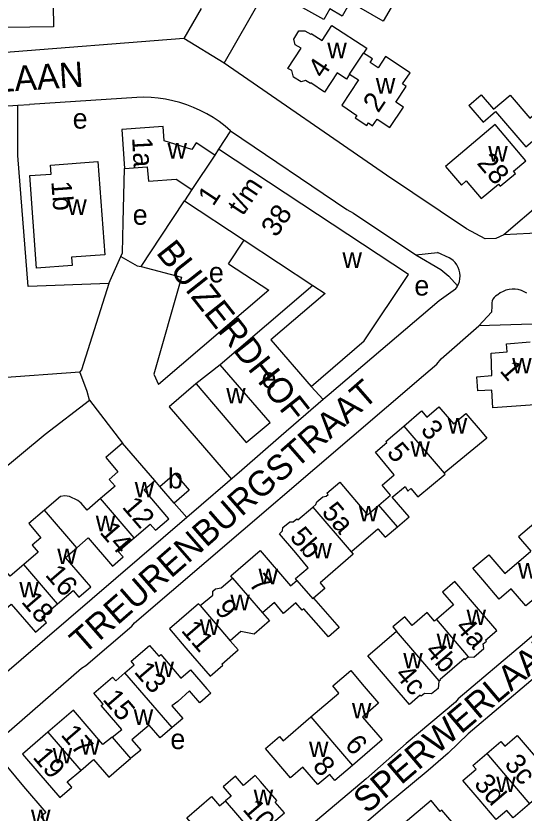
# Model space of a CAD drawing. Extents: x 161775 to 163181, y 382878 to 383925.
# Drawn here: x 162330.5 to 162431.4, y 383379.1 to 383537.4 of the extents above; entities that cross this region are included whole.
import ezdxf

# ---------------------------------------------------------------- set-up
doc = ezdxf.new("R2010")
doc.units = 0
for name, color, linetype in [('BLT_Basislijn', 7, 'Continuous'), ('BLT_Bebouwing', 7, 'Continuous'), ('BLT_Centroide', 7, 'Continuous'), ('BLT_Huisnummer', 7, 'Continuous'), ('BLT_Huisnummer_ tussenligend', 7, 'Continuous'), ('BLT_Huisnummer_reeks', 7, 'Continuous'), ('BLT_Onderverdeling_panden', 7, 'Continuous'), ('BLT_Straatnaam', 7, 'Continuous'), ('BLT_Vlakafsluiter', 7, 'Continuous')]:
    doc.layers.add(name, color=color, linetype=linetype)

msp = doc.modelspace()

# ---------------------------------------------------------------- linework, layer by layer
at = {"layer": 'BLT_Basislijn'}
for p, q in [((162371.87, 383527.99), (162382.43, 383546.52)), ((162367.27, 383538.86), (162363.82, 383532.92)), ((162363.82, 383532.92), (162326.4, 383529.95)), ((162404.09, 383505.78), (162371.87, 383527.99)), ((162326.23, 383519.34), (162330.87, 383519.66)), ((162330.87, 383519.66), (162333.17, 383519.81)), ((162354.48, 383521.19), (162333.17, 383519.81)), ((162457.69, 383519.94), (162427.38, 383493.93)), ((162373.13, 383514.58), (162370.75, 383510.9)), ((162420, 383495.12), (162404.09, 383505.78)), ((162359.34, 383493.66), (162363.97, 383500.65)), ((162423.66, 383493.13), (162420, 383495.12)), ((162372.71, 383488.18), (162375.8, 383492.86)), ((162425.81, 383493.17), (162423.66, 383493.13)), ((162427.38, 383493.93), (162425.81, 383493.17)), ((162348.94, 383484.25), (162351.33, 383489.59)), ((162409.9, 383489.96), (162414.18, 383490.39)), ((162409.9, 383489.96), (162414.9, 383487.01)), ((162416.54, 383489.36), (162414.18, 383490.39)), ((162372.71, 383488.18), (162380.72, 383482.91)), ((162354.57, 383487.77), (162355.35, 383487.64)), ((162355.35, 383487.64), (162363.39, 383485.52)), ((162363.39, 383485.52), (162357.86, 383466.22)), ((162389.47, 383483.86), (162371.03, 383468.13)), ((162380.72, 383482.91), (162358.81, 383464.21)), ((162417.76, 383483.13), (162414.52, 383480.78)), ((162439.94, 383476.36), (162422.42, 383475.81)), ((162282.95, 383462.44), (162343.17, 383466.7)), ((162357.86, 383466.22), (162358.81, 383464.21)), ((162366.24, 383464.35), (162360.91, 383459.75)), ((162389.1, 383463.77), (162391.49, 383461.2)), ((162345.08, 383461.11), (162351.68, 383452.54)), ((162391.49, 383461.2), (162383.2, 383453.99)), ((162360.91, 383459.75), (162373.3, 383445.39)), ((162359.11, 383443.95), (162358.08, 383445.1)), ((162364.43, 383437.79), (162361.95, 383440.66)), ((162364.43, 383437.79), (162308.93, 383390.15))]:
    msp.add_line(p, q, dxfattribs=at)
for points in [[(162373.13, 383514.58), (162372.02, 383515.52), (162370.85, 383516.39), (162369.64, 383517.19), (162368.39, 383517.93), (162367.1, 383518.6), (162365.78, 383519.19), (162364.42, 383519.71), (162363.04, 383520.16), (162361.63, 383520.53), (162360.21, 383520.82), (162358.77, 383521.03), (162357.33, 383521.16), (162355.88, 383521.22), (162354.48, 383521.19)], [(162332.94, 383483.65), (162330.87, 383509.66), (162330.87, 383519.66)], [(162373.13, 383514.58), (162396.2, 383498.97), (162397.54, 383498.24), (162409.9, 383489.96)], [(162351.33, 383489.59), (162351.67, 383490.34), (162351.82, 383496.43), (162352.09, 383507.07)], [(162355.35, 383487.64), (162359.34, 383493.66)], [(162351.33, 383489.59), (162354.57, 383487.77)], [(162418.19, 383483.78), (162418.36, 383484.1), (162418.55, 383484.64), (162418.67, 383485.2), (162418.71, 383485.77), (162418.66, 383486.34), (162418.54, 383486.9), (162418.34, 383487.44), (162418.07, 383487.94), (162417.73, 383488.4), (162417.33, 383488.81), (162416.88, 383489.16), (162416.54, 383489.36)], [(162414.9, 383487.01), (162416.43, 383485.68), (162418.19, 383483.78)], [(162348.94, 383484.25), (162332.94, 383483.65)], [(162348.94, 383484.25), (162343.51, 383467.08), (162343.17, 383466.7)], [(162417.76, 383483.13), (162418.1, 383483.59), (162418.19, 383483.78)], [(162426.04, 383481.9), (162425.71, 383481.71), (162425.43, 383481.45), (162425.2, 383481.14), (162425.05, 383480.79), (162424.97, 383480.42), (162424.97, 383480.03), (162425.02, 383479.76)], [(162431.97, 383482.31), (162431.43, 383482.62), (162430.86, 383482.87), (162430.26, 383483.03), (162429.65, 383483.12), (162429.02, 383483.13), (162428.41, 383483.06), (162427.8, 383482.91), (162427.22, 383482.68), (162426.68, 383482.39), (162426.18, 383482.02), (162426.04, 383481.9)], [(162414.52, 383480.78), (162392.68, 383462.23), (162391.49, 383461.2)], [(162425.02, 383479.76), (162424.92, 383478.53), (162422.42, 383475.81)], [(162458.26, 383455.1), (162467.27, 383444.75), (162467.36, 383443.86), (162431.49, 383412.9), (162418.33, 383401.81), (162417.78, 383401.1), (162408.01, 383392.9), (162400.04, 383385.87), (162360.11, 383352.24), (162353.15, 383345.86), (162352.04, 383345.68), (162316.39, 383381.73), (162316.3, 383384.27), (162343.54, 383407.84), (162344.4, 383408.4), (162353.54, 383416.23), (162354.02, 383416.86), (162411.46, 383465.98), (162414.05, 383468.24), (162414.93, 383469.26), (162422.42, 383475.81)], [(162345.08, 383461.11), (162344.65, 383462.79), (162343.17, 383466.7)], [(162286.02, 383413.98), (162326.83, 383446.53), (162336.32, 383454.32), (162345.08, 383461.11)], [(162383.2, 383453.99), (162375.35, 383447.16), (162364.43, 383437.79)], [(162495.64, 383411.76), (162472.36, 383438.61), (162471.64, 383438.47), (162459.3, 383427.81), (162454.29, 383423.76), (162452.92, 383422.41), (162420.3, 383394.84), (162416.34, 383390.96), (162412.36, 383387.52), (162403.8, 383380.46), (162382.22, 383361.95), (162376.07, 383356.94), (162357.64, 383341.11), (162357.5, 383340.43), (162364.56, 383332.99), (162388.13, 383309.03), (162393.36, 383303.95)]]:
    msp.add_lwpolyline(points, dxfattribs=at)
at = {"layer": 'BLT_Bebouwing'}
for p, q in [((162370.75, 383510.9), (162369.98, 383509.74)), ((162365.46, 383502.91), (162363.97, 383500.65)), ((162363.97, 383500.65), (162375.8, 383492.86)), ((162366.24, 383464.35), (162366.28, 383464.3)), ((162366.28, 383464.3), (162376.21, 383452.69)), ((162376.21, 383452.69), (162380.96, 383456.62)), ((162358.08, 383445.1), (162351.68, 383452.54)), ((162361.95, 383440.66), (162359.11, 383443.95))]:
    msp.add_line(p, q, dxfattribs=at)
for points in [[(162321, 383571.11), (162328.99, 383571.18), (162328.95, 383575.83), (162340.08, 383575.93), (162340.18, 383563.69), (162340.29, 383558.17), (162340.51, 383539.52), (162337.92, 383539.49), (162337.98, 383535.18), (162323.79, 383535), (162323.75, 383537.58), (162320.5, 383537.54), (162320.54, 383534.87)], [(162404.54, 383539.34), (162405.01, 383539.07), (162403.43, 383536.32), (162396.89, 383540.09), (162395.3, 383537.34), (162392.84, 383538.76), (162391.62, 383536.64), (162387.5, 383539.01), (162388.73, 383541.13), (162386.93, 383542.16), (162387.87, 383544.22), (162389.01, 383545.56), (162390.3, 383547.8)], [(162396.77, 383525.83), (162396.11, 383524.84), (162394.29, 383526.06), (162391.75, 383522.25), (162389.09, 383524.09), (162389.01, 383523.95), (162387.99, 383524.54), (162387.16, 383524.32), (162385.65, 383525.19), (162385.3, 383526.51), (162384.51, 383526.96), (162387.16, 383530.97), (162385.96, 383531.66), (162385.67, 383532.75), (162386.65, 383534.45), (162387.84, 383534.45), (162389.03, 383533.77), (162389.13, 383533.92), (162391.32, 383532.51), (162393.21, 383535.47), (162400.2, 383530.98), (162399.55, 383530)], [(162407.43, 383519.24), (162405.91, 383520.26), (162407.99, 383523.39), (162407.28, 383523.87), (162408.76, 383526.09), (162403.9, 383529.32), (162402.4, 383527.07), (162400.82, 383528.12), (162401.3, 383528.83), (162399.55, 383530)], [(162396.77, 383525.83), (162398.52, 383524.66), (162395.19, 383519.65), (162398.22, 383517.64), (162397.89, 383517.13), (162400.15, 383515.63), (162400.48, 383516.12), (162401.31, 383515.57), (162402.2, 383516.91), (162404.75, 383515.21), (162407.43, 383519.24)], [(162420.44, 383519.57), (162422.9, 383521.69), (162425.36, 383518.84), (162428.62, 383521.65), (162432.56, 383517.06), (162435.02, 383519.17), (162433.32, 383521.15), (162436.84, 383524.17)], [(162420.44, 383519.57), (162423.28, 383516.27), (162425.74, 383518.39), (162431.77, 383511.38), (162434.86, 383514.04), (162438.91, 383509.34), (162445.06, 383514.63), (162444.71, 383515.04)], [(162369.98, 383509.74), (162366.29, 383512.16), (162365.41, 383510.83), (162359.94, 383512.6), (162359.75, 383515.42), (162351.52, 383514.81), (162352.09, 383507.07)], [(162428.52, 383512.42), (162425.65, 383515.81), (162419.65, 383510.72), (162415.83, 383507.49), (162418.96, 383503.8), (162419.93, 383504.63), (162422.9, 383501.13), (162426.29, 383504), (162426.68, 383503.55), (162429.68, 383506.1), (162429.31, 383506.54), (162431.75, 383508.61), (162428.52, 383512.42)], [(162389.1, 383463.77), (162399.68, 383472.84), (162408.44, 383486.05), (162387.28, 383500), (162370.75, 383510.9)], [(162333.26, 383505.67), (162337.52, 383505.98), (162337.39, 383507.77), (162346.79, 383508.46), (162348.15, 383489.95), (162341.53, 383489.47), (162341.65, 383487.79), (162334.61, 383487.27), (162333.26, 383505.67)], [(162352.09, 383507.07), (162356.59, 383507.41), (162356.8, 383504.58), (162362.31, 383504.99), (162365.46, 383502.91)], [(162375.8, 383492.86), (162389.47, 383483.86)], [(162389.47, 383483.86), (162391.9, 383482.25), (162381.15, 383473.04), (162389.1, 383463.77)], [(162433.51, 383460.4), (162433.51, 383460.13), (162425.23, 383459.57), (162424.98, 383463.1), (162422.25, 383462.91), (162422.04, 383465.74), (162425.02, 383465.96), (162424.88, 383470.43), (162428.02, 383470.66), (162427.91, 383472.3), (162432.62, 383472.64)], [(162380.96, 383456.62), (162371.03, 383468.13), (162366.24, 383464.35)], [(162407.52, 383455.9), (162411.06, 383458.94), (162412.11, 383457.72), (162414.5, 383459.78), (162417.42, 383456.38), (162419.81, 383458.44), (162423.07, 383454.64), (162424.01, 383453.55), (162415.51, 383446.6)], [(162402.53, 383440.23), (162404.88, 383442.25), (162403.21, 383444.2), (162405.6, 383446.25), (162401.91, 383450.75), (162404.14, 383452.66), (162403.98, 383452.85), (162407.52, 383455.9)], [(162351.68, 383452.54), (162348.34, 383449.67), (162350.75, 383446.86), (162349.01, 383445.36), (162350.18, 383443.99), (162347.32, 383441.53)], [(162359.11, 383443.95), (162362.06, 383446.49), (162364.9, 383443.19), (162361.95, 383440.66)], [(162406.24, 383435.92), (162408.56, 383437.92), (162405.22, 383441.8), (162407.79, 383443.94), (162408.31, 383443.04), (162408.93, 383443.55), (162410.3, 383441.9), (162415.7, 383446.38), (162415.51, 383446.6)], [(162354, 383433.76), (162357.17, 383436.48), (162358.22, 383435.26), (162360.87, 383437.54), (162355.95, 383443.26), (162358.08, 383445.1)], [(162389.44, 383439.84), (162390.08, 383440.39), (162390.25, 383440.89), (162391.43, 383441.9), (162392.1, 383442.03), (162392.47, 383442.35), (162392.26, 383442.6), (162394.79, 383444.78), (162400.32, 383438.33), (162402.53, 383440.23)], [(162347.32, 383441.53), (162344.65, 383439.24), (162343.47, 383440.61), (162342.79, 383441.19), (162341.12, 383441.94), (162340.23, 383442.08), (162339.34, 383441.95), (162336.21, 383439.26)], [(162438.81, 383424.03), (162442.28, 383426.99), (162441.23, 383428.23), (162443.66, 383430.3), (162440.76, 383433.7), (162443.16, 383435.75), (162439.91, 383439.55), (162437.93, 383441.87), (162434.82, 383439.21), (162435.52, 383438.39), (162430.3, 383433.92), (162432.73, 383431.07)], [(162336.21, 383439.26), (162333.08, 383436.57), (162335.48, 383433.76), (162333.74, 383432.26), (162334.91, 383430.9), (162332.06, 383428.45)], [(162386.29, 383425.3), (162385.99, 383425.65), (162388.52, 383427.82), (162386.07, 383430.77), (162382.81, 383434.56), (162383.46, 383435.12), (162383.51, 383435.78), (162384.87, 383436.95), (162385.52, 383436.9), (162386.27, 383437.54), (162386.47, 383437.3), (162389.44, 383439.84)], [(162397.06, 383430.98), (162397.19, 383431.09), (162402.38, 383435.55), (162403.84, 383433.85), (162406.24, 383435.92)], [(162342.63, 383431.79), (162344.88, 383433.73), (162349.68, 383428.15), (162351.77, 383429.95), (162350.83, 383431.03), (162354, 383433.76)], [(162338.76, 383420.65), (162341.84, 383423.31), (162342.98, 383421.98), (162345.38, 383424.05), (162340.38, 383429.86), (162342.63, 383431.79)], [(162373.52, 383425.77), (162373.15, 383426.2), (162379.01, 383431.23), (162385.03, 383424.22), (162386.29, 383425.3)], [(162438.81, 383424.03), (162435.27, 383421.01), (162434.17, 383422.29), (162431.75, 383420.22), (162428.85, 383423.62), (162426.44, 383421.57), (162423.2, 383425.38), (162421.22, 383427.7), (162424.39, 383430.4), (162427.58, 383426.67), (162432.73, 383431.07)], [(162397.06, 383430.98), (162397.47, 383430.49), (162390.9, 383424.84), (162391.87, 383423.7), (162389.62, 383421.76)], [(162332.06, 383428.45), (162329.37, 383426.14), (162328.2, 383427.51), (162326.45, 383426.01), (162324.05, 383428.81), (162320.99, 383426.19)], [(162367.09, 383420.28), (162369.57, 383422.39), (162369.63, 383423.18), (162370.15, 383423.62), (162371.26, 383423.83), (162373.52, 383425.77)], [(162420.3, 383410.15), (162421.41, 383410.06), (162423.44, 383411.8), (162423.28, 383412.7), (162423.92, 383413.25), (162423.77, 383413.42), (162425.99, 383415.32), (162422.75, 383419.12), (162417.66, 383425.09), (162415.18, 383422.97), (162417.36, 383420.42), (162413.99, 383417.54)], [(162389.62, 383421.76), (162394.67, 383415.94), (162392.54, 383414.09), (162387.7, 383419.67), (162387.36, 383419.37), (162386.09, 383420.84), (162383.66, 383418.75), (162381.84, 383420.88), (162379.48, 383418.83)], [(162327.41, 383418.71), (162329.57, 383420.57), (162334.36, 383414.99), (162336.6, 383416.92), (162335.67, 383418), (162338.76, 383420.65)], [(162367.09, 383420.28), (162366.77, 383420.65), (162360.97, 383415.66), (162364.23, 383411.87), (162369.04, 383406.27), (162371.59, 383408.47), (162371.4, 383408.69), (162374.65, 383411.48), (162373.07, 383413.32)], [(162379.48, 383418.83), (162380.84, 383417.24), (162377.83, 383414.65), (162375.16, 383415.12), (162373.07, 383413.32)], [(162413.99, 383417.54), (162413.6, 383417.21), (162412.15, 383418.9), (162409.17, 383416.36), (162407.72, 383418.05), (162405.37, 383416.05), (162406.09, 383415.2)], [(162414.54, 383405.34), (162414.46, 383405.27), (162414.34, 383403.85), (162413.05, 383402.74), (162411.6, 383402.86), (162410.95, 383402.31), (162410.79, 383402.5), (162408.62, 383400.66), (162405.38, 383404.46), (162400.37, 383410.35), (162406.09, 383415.2)], [(162352.16, 383406.95), (162354, 383408.53), (162353.38, 383409.25), (162357.02, 383412.38), (162358.87, 383410.23), (162359.27, 383410.57), (162363.28, 383405.91), (162365.17, 383407.54), (162368.43, 383403.75), (162369.19, 383402.88), (162367, 383401), (162364.98, 383403.35), (162362.67, 383401.27), (162361.47, 383400.41), (162363.63, 383397.9), (162361.51, 383396.08)], [(162414.54, 383405.34), (162414.81, 383405.58), (162414.71, 383405.7), (162419.51, 383409.8), (162419.67, 383409.61), (162420.3, 383410.15)], [(162389.09, 383398.19), (162394.64, 383402.93), (162393.44, 383404.34), (162396.99, 383407.38), (162399.28, 383404.7), (162402.52, 383400.9), (162399.33, 383398.17), (162403.22, 383393.61), (162397.32, 383388.56)], [(162349.61, 383394.17), (162351.52, 383395.71), (162350.71, 383396.64), (162347.45, 383400.43), (162347.83, 383400.75), (162345.99, 383402.89), (162349.71, 383406.09), (162350.33, 383405.38), (162352.16, 383406.95)], [(162349.61, 383394.17), (162347.79, 383392.71), (162341.93, 383399.54), (162336.86, 383395.18)], [(162397.32, 383388.56), (162393.81, 383385.57), (162392.8, 383386.76), (162390.43, 383384.74), (162387.47, 383388.21), (162385.01, 383386.11), (162380.04, 383391.93), (162382.83, 383394.31), (162383.55, 383393.46), (162389.09, 383398.19)], [(162361.51, 383396.08), (162359.14, 383394.04), (162356.99, 383396.54), (162353.54, 383393.63), (162355.29, 383391.61), (162353.27, 383389.91)], [(162336.86, 383395.18), (162331.78, 383390.82), (162335.04, 383387.03), (162339.19, 383382.2), (162341.58, 383384.26), (162340.71, 383385.27), (162343.39, 383387.57)], [(162424.01, 383390.92), (162426.8, 383393.29), (162427.57, 383392.39), (162430.05, 383394.5), (162437.15, 383386.17), (162439.24, 383387.95), (162442.52, 383384.1), (162439.98, 383381.95), (162437.32, 383385.07), (162432.49, 383380.96)], [(162343.39, 383387.57), (162345.92, 383389.75), (162348.94, 383386.23), (162351.49, 383388.42), (162353.27, 383389.91)], [(162432.49, 383380.96), (162429.22, 383378.17), (162428, 383379.6), (162425.89, 383377.81), (162422.51, 383381.78), (162419.27, 383385.59), (162421.86, 383387.8), (162421.22, 383388.55), (162424.01, 383390.92)], [(162341.1, 383370.08), (162337.23, 383366.91), (162322.63, 383381.72), (162322.74, 383383.1), (162328.81, 383388.22), (162332.04, 383384.4), (162336.43, 383379.21), (162335.45, 383378.38), (162338.42, 383374.87), (162340.86, 383376.93), (162344.38, 383372.77), (162341.1, 383370.08)], [(162378.23, 383374.41), (162383.81, 383379.17), (162381.99, 383381.29), (162382.3, 383381.56), (162379.06, 383385.36), (162378.02, 383386.57), (162375.69, 383384.58), (162374.1, 383386.44), (162371.64, 383384.33), (162373.22, 383382.48), (162372.13, 383381.55)], [(162378.23, 383374.41), (162372.66, 383369.65), (162370.86, 383371.76), (162370.45, 383371.4), (162367.2, 383375.2), (162366.16, 383376.42), (162366.03, 383376.31), (162364.43, 383378.18), (162369.33, 383382.37), (162370.91, 383380.51), (162372.13, 383381.55)], [(162413.5, 383369.7), (162414.65, 383370.68), (162416.2, 383368.84), (162420.91, 383372.85), (162418.31, 383375.89), (162415.07, 383379.7), (162414.76, 383379.44), (162412.93, 383381.59), (162407.39, 383376.88)]]:
    msp.add_lwpolyline(points, dxfattribs=at)
at = {"layer": 'BLT_Onderverdeling_panden'}
for p, q in [((162396.77, 383525.83), (162399.55, 383530)), ((162369.98, 383509.74), (162365.46, 383502.91)), ((162407.52, 383455.9), (162415.51, 383446.6)), ((162354, 383433.76), (162347.32, 383441.53)), ((162342.63, 383431.79), (162336.21, 383439.26)), ((162389.44, 383439.84), (162397.06, 383430.97)), ((162406.24, 383435.92), (162402.53, 383440.23)), ((162338.76, 383420.65), (162332.06, 383428.45)), ((162373.52, 383425.77), (162379.48, 383418.83)), ((162367.09, 383420.28), (162373.07, 383413.32)), ((162413.99, 383417.54), (162420.3, 383410.15)), ((162414.54, 383405.34), (162406.09, 383415.2)), ((162361.51, 383396.08), (162352.16, 383406.95)), ((162389.09, 383398.19), (162397.32, 383388.56)), ((162336.86, 383395.18), (162343.39, 383387.57)), ((162349.61, 383394.17), (162353.27, 383389.91)), ((162424.01, 383390.92), (162432.49, 383380.96)), ((162378.23, 383374.41), (162372.13, 383381.55))]:
    msp.add_line(p, q, dxfattribs=at)
msp.add_lwpolyline([(162386.29, 383425.3), (162389.45, 383421.62), (162389.62, 383421.76)], dxfattribs=at)
at = {"layer": 'BLT_Vlakafsluiter'}
for p, q in [((162371.87, 383527.99), (162363.82, 383532.92)), ((162440.69, 383494.57), (162427.38, 383493.93))]:
    msp.add_line(p, q, dxfattribs=at)

# ---------------------------------------------------------------- texts
at = {"layer": 'BLT_Centroide'}
for s, p in [('w', (162392.33, 383528.97)), ('w', (162401.97, 383521.95)), ('e', (162341.77, 383515)), ('w', (162360.6, 383509.06)), ('w', (162424.29, 383508.47)), ('w', (162340.7, 383497.86)), ('e', (162353.69, 383495.9)), ('w', (162395.34, 383487.34)), ('e', (162368.81, 383484.47)), ('e', (162409.61, 383481.85)), ('w', (162429.04, 383466.38)), ('e', (162379.28, 383463.52)), ('w', (162372.26, 383460.45)), ('w', (162416.25, 383454.44)), ('w', (162408.84, 383449.86)), ('b', (162360.67, 383443.56)), ('w', (162354.09, 383441.78)), ('w', (162398.59, 383437)), ('w', (162346.36, 383435.06)), ('w', (162389.38, 383429.67)), ('w', (162338.72, 383428.52)), ('w', (162430.18, 383425.66)), ('w', (162378.68, 383424.53)), ('w', (162331.18, 383421.91)), ('w', (162373.09, 383419.38)), ('w', (162419.98, 383416.42)), ('w', (162367.02, 383414.48)), ('w', (162414.04, 383411.66)), ('w', (162407.41, 383407.84)), ('w', (162358.02, 383406.09)), ('w', (162397.22, 383397.91)), ('w', (162353.89, 383396.59)), ('e', (162361.17, 383391.8)), ('w', (162343.32, 383390.69)), ('w', (162388.7, 383390.22)), ('w', (162337.8, 383388.95)), ('w', (162425.88, 383383.27)), ('w', (162377.72, 383380.66)), ('w', (162333.5, 383376.67))]:
    msp.add_text(s, height=4, dxfattribs=at).set_placement(p)
at = {"layer": 'BLT_Huisnummer'}
for s, rotation, p in [('4', 56.3099, (162391.51, 383524.79)), ('2', 56.3591, (162402.45, 383517.97)), ('1a', 273.0642, (162353.57, 383513.21)), ('28', 310.2503, (162421.89, 383508.09)), ('1b', 274.1936, (162337.52, 383504.5)), ('1', 310.6771, (162426.42, 383466.86)), ('3', 310.6836, (162410.7, 383455.08)), ('5', 310.6852, (162403.98, 383450.6)), ('12', 310.8568, (162351.43, 383439.81)), ('5a', 310.6845, (162391.04, 383438.75)), ('5b', 310.6771, (162384.7, 383433.82)), ('16', 310.6926, (162336.17, 383426.33)), ('7', 310.6692, (162376.59, 383424.52)), ('11', 310.6821, (162363.17, 383415.28)), ('4a', 310.4984, (162417.58, 383415.88)), ('4b', 310.4969, (162411.56, 383411.15)), ('13', 310.6821, (162353.82, 383407.07)), ('4c', 310.482, (162405.6, 383406.47)), ('6', 310.4922, (162395.64, 383392.58)), ('19', 310.6825, (162333.69, 383390.12)), ('8', 310.4869, (162389.24, 383388.32)), ('3c', 310.3956, (162427.34, 383388.72)), ('3d', 310.4013, (162421.29, 383384.79)), ('10', 310.4835, (162375.38, 383379.77))]:
    msp.add_text(s, height=4, rotation=rotation, dxfattribs=at).set_placement(p)
at = {"layer": 'BLT_Huisnummer_ tussenligend'}
for s, rotation, p in [('14', 310.8568, (162346.98, 383434.79)), ('18', 310.6926, (162331.43, 383420.99)), ('9', 310.6692, (162369.8, 383419.48)), ('15', 310.6771, (162347.58, 383401.6)), ('17', 310.6771, (162339.27, 383394.57))]:
    msp.add_text(s, height=4, rotation=rotation, dxfattribs=at).set_placement(p)
at = {"layer": 'BLT_Huisnummer_reeks'}
for s, p in [('t/m', (162375.55, 383497.52)), ('1', (162369.68, 383499.43)), ('38', (162382.22, 383493.25))]:
    msp.add_text(s, height=4, rotation=56.5143, dxfattribs=at).set_placement(p)
at = {"layer": 'BLT_Straatnaam'}
for s, height, rotation, p in [('FAZANTLAAN', 5, 3.8076, (162300.68, 383520.46)), ('BUIZERDHOF', 5, 308.3235, (162358.19, 383490.33)), ('TREURENBURGSTRAAT', 5, 41.2002, (162343.96, 383410.42)), ('SPERWERLAAN', 4.9999, 40.3065, (162400.18, 383378.81))]:
    msp.add_text(s, height=height, rotation=rotation, dxfattribs=at).set_placement(p)

doc.saveas('drawing.dxf')
